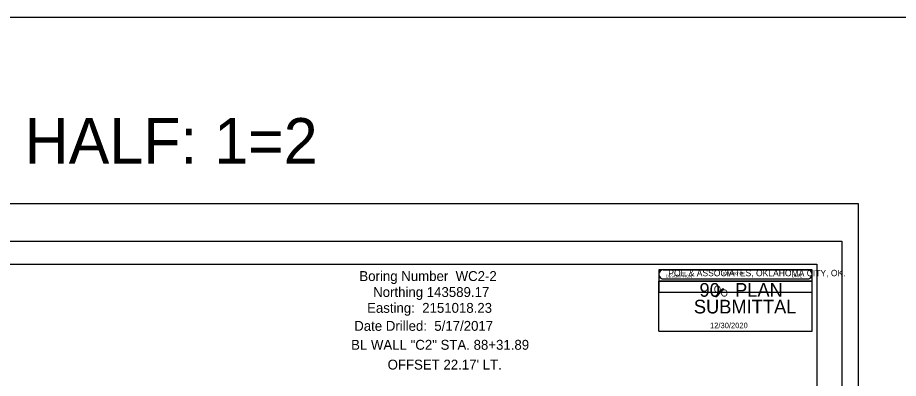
# Model space of a CAD drawing. Extents: x -2 to 138, y 24 to 58.
# Drawn here: x 24.17 to 43.5, y 50.14 to 58.05 of the extents above; entities that cross this region are included whole.
import ezdxf

# ---------------------------------------------------------------- set-up
doc = ezdxf.new("R2010")
doc.units = 0
for name, color, linetype in [('S', 7, 'Continuous'), ('SHT_Plot_Shape_Full', 7, 'Continuous'), ('SHT_Plot_Shape_Half', 7, 'Continuous'), ('SHT_Sheet_Border', 7, 'Continuous'), ('SHT_Stamp_90_Submit', 7, 'Continuous'), ('SHT_Stamp_Rev_Block', 7, 'Continuous')]:
    doc.layers.add(name, color=color, linetype=linetype)

msp = doc.modelspace()

# ---------------------------------------------------------------- linework, layer by layer
at = {"layer": 'S'}
msp.add_lwpolyline([(-2.212, 26.92), (137.529, 26.92), (137.529, 58.049), (-2.212, 58.049)], close=True, dxfattribs=at)
at = {"layer": 'SHT_Plot_Shape_Full'}
msp.add_lwpolyline([(6.624, 53.971), (42.624, 53.971), (42.624, 29.971), (6.624, 29.971)], close=True, dxfattribs=at)
at = {"layer": 'SHT_Plot_Shape_Half'}
msp.add_lwpolyline([(8.262, 53.146), (42.262, 53.146), (42.262, 31.146), (8.262, 31.146)], close=True, dxfattribs=at)
at = {"layer": 'SHT_Sheet_Border'}
msp.add_lwpolyline([(10.212, 52.646), (41.712, 52.646), (41.712, 31.646), (10.212, 31.646)], close=True, dxfattribs=at)
at = {"layer": 'SHT_Stamp_90_Submit'}
for p, q in [((38.343, 52.522), (41.509, 52.522)), ((38.243, 52.272), (41.609, 52.272)), ((38.243, 51.173), (38.243, 52.272)), ((38.343, 52.322), (41.509, 52.322)), ((41.609, 51.173), (41.609, 52.272)), ((39.486, 51.934), (39.641, 52.107)), ((39.504, 51.934), (39.659, 52.107)), ((39.509, 51.934), (39.664, 52.107)), ((39.516, 51.934), (39.672, 52.107)), ((39.641, 52.107), (39.672, 52.107)), ((39.486, 51.934), (39.516, 51.934)), ((38.243, 51.173), (41.609, 51.173))]:
    msp.add_line(p, q, dxfattribs=at)
for centre, start, end in [((38.343, 52.422), 89.9952, 270), ((41.509, 52.422), 270, 90.0048)]:
    msp.add_arc(centre, 0.1, start, end, dxfattribs=at)
at = {"layer": 'SHT_Stamp_Rev_Block'}
for p, q in [((38.243, 52.522), (38.243, 52.022)), ((41.609, 52.522), (38.243, 52.522)), ((41.609, 52.022), (41.609, 52.522)), ((41.609, 52.272), (38.243, 52.272)), ((41.609, 52.022), (38.243, 52.022))]:
    msp.add_line(p, q, dxfattribs=at)

# ---------------------------------------------------------------- texts
for s, p in [('Boring Number  WC2-2', (31.672, 52.275)), ('Northing 143589.17', (31.974, 51.925)), ('Easting:  2151018.23', (31.841, 51.578)), ('Date Drilled:  5/17/2017', (31.559, 51.183)), ('BL WALL "C2" STA. 88+31.89', (31.49, 50.768)), ("OFFSET 22.17' LT.", (32.292, 50.334))]:
    msp.add_text(s, height=0.217).set_placement(p)
at = {"layer": 'S'}
msp.add_text('FULL: 1=1   HALF: 1=2', height=1, dxfattribs=at).set_placement((16.93, 54.847))
at = {"layer": 'SHT_Stamp_90_Submit'}
for s, height, p in [('POE & ASSOCIATES, OKLAHOMA CITY, OK.', 0.14, (38.453, 52.38)), ('90   PLAN', 0.3, (39.138, 51.93)), ('O', 0.153, (39.451, 52.019)), ('O', 0.153, (39.603, 51.935)), ('SUBMITTAL', 0.3, (39.014, 51.564)), ('12/30/2020', 0.12, (39.368, 51.241))]:
    msp.add_text(s, height=height, dxfattribs=at).set_placement(p)
at = {"layer": 'SHT_Stamp_Rev_Block'}
for s, height, p in [('DESCRIPTION', 0.05999, (38.403, 52.351)), ('REVISIONS', 0.06, (39.651, 52.41)), ('DATE', 0.06, (41.172, 52.355))]:
    msp.add_text(s, height=height, dxfattribs=at).set_placement(p)

doc.saveas('drawing.dxf')
